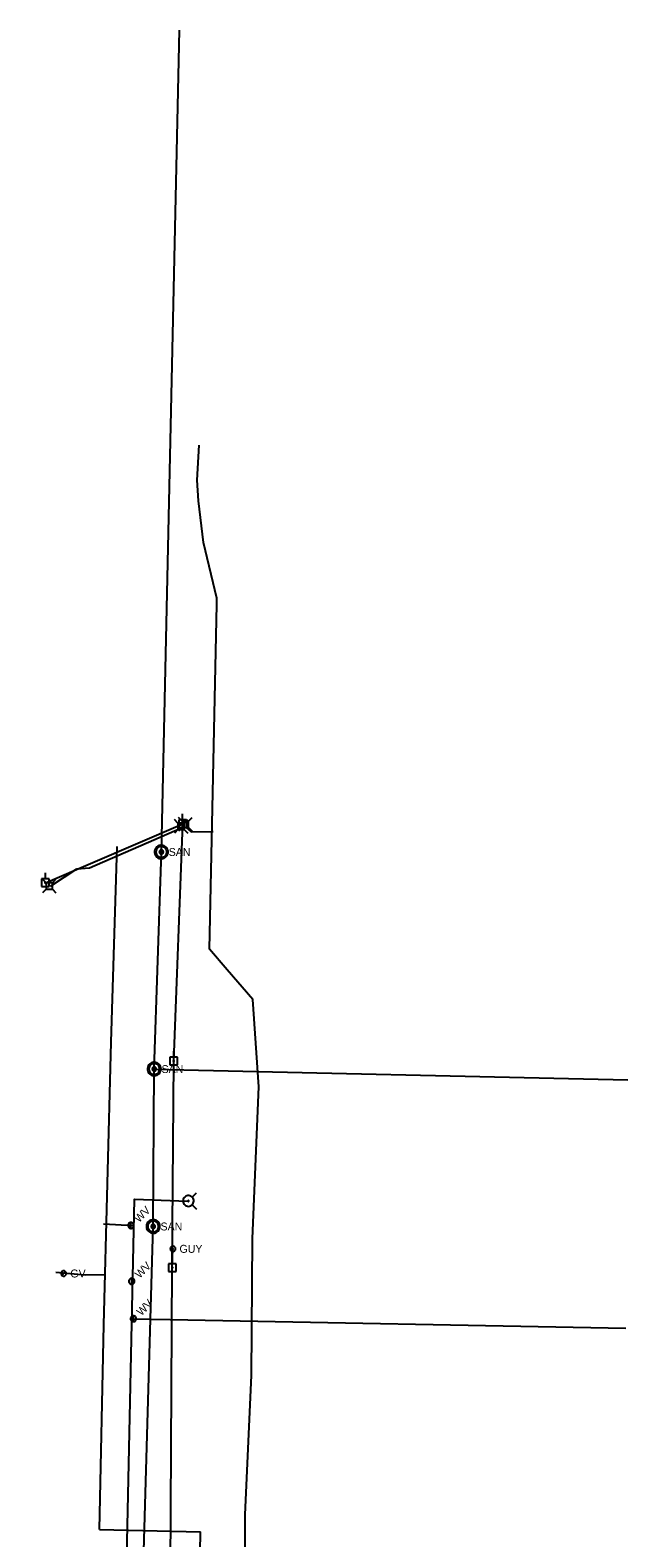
# Model space of a CAD drawing. Extents: x 596028 to 606371, y 330010 to 403088.
# Drawn here: x 596433 to 596723, y 343578 to 344310 of the extents above; entities that cross this region are included whole.
import ezdxf

# ---------------------------------------------------------------- set-up
doc = ezdxf.new("R2010")
doc.units = 0
for name, color, linetype in [('E_UTL_EGuyWire', 7, 'Continuous'), ('E_UTL_EPowerPole', 7, 'Continuous'), ('E_UTL_FO_UG', 7, 'Continuous'), ('E_UTL_G', 7, 'Continuous'), ('E_UTL_G_UG', 7, 'Continuous'), ('E_UTL_Overhead', 7, 'Continuous'), ('E_UTL_SAN_MH', 7, 'Continuous'), ('E_UTL_SAN_UG', 7, 'Continuous'), ('E_UTL_T', 7, 'Continuous'), ('E_UTL_T_UG', 7, 'Continuous'), ('E_UTL_W', 7, 'Continuous'), ('E_UTL_W_UG', 7, 'Continuous'), ('E_UTL_WHydrant', 7, 'Continuous')]:
    doc.layers.add(name, color=color, linetype=linetype)

msp = doc.modelspace()

# ---------------------------------------------------------------- linework, layer by layer
at = {"layer": 'E_UTL_EGuyWire'}
msp.add_line((596502.11, 343708.76), (596502.4, 343717.87), dxfattribs=at)
for points in [[(596503.68, 343717.87), (596503.66, 343718.12), (596503.59, 343718.35), (596503.48, 343718.57), (596503.32, 343718.76), (596503.14, 343718.92), (596502.93, 343719.04), (596502.7, 343719.12), (596502.46, 343719.15), (596502.21, 343719.14), (596501.98, 343719.09), (596501.75, 343718.98), (596501.56, 343718.84), (596501.39, 343718.67), (596501.26, 343718.46), (596501.16, 343718.23), (596501.12, 343717.99), (596501.12, 343717.75), (596501.16, 343717.51), (596501.26, 343717.28), (596501.39, 343717.08), (596501.56, 343716.9), (596501.75, 343716.76), (596501.98, 343716.66), (596502.21, 343716.6), (596502.46, 343716.59), (596502.7, 343716.63), (596502.93, 343716.71), (596503.14, 343716.83), (596503.32, 343716.99), (596503.48, 343717.18), (596503.59, 343717.4), (596503.66, 343717.63), (596503.68, 343717.87)], [(596502.56, 343717.87), (596502.55, 343717.9), (596502.54, 343717.93), (596502.53, 343717.96), (596502.51, 343717.98), (596502.49, 343718), (596502.46, 343718.02), (596502.43, 343718.03), (596502.4, 343718.03), (596502.37, 343718.03), (596502.34, 343718.02), (596502.32, 343718.01), (596502.29, 343717.99), (596502.27, 343717.97), (596502.25, 343717.95), (596502.24, 343717.92), (596502.24, 343717.89), (596502.24, 343717.86), (596502.24, 343717.83), (596502.25, 343717.8), (596502.27, 343717.77), (596502.29, 343717.75), (596502.32, 343717.73), (596502.34, 343717.72), (596502.37, 343717.71), (596502.4, 343717.71), (596502.43, 343717.72), (596502.46, 343717.73), (596502.49, 343717.74), (596502.51, 343717.76), (596502.53, 343717.79), (596502.54, 343717.81), (596502.55, 343717.84), (596502.56, 343717.87)]]:
    msp.add_lwpolyline(points, dxfattribs=at)
at = {"layer": 'E_UTL_EPowerPole'}
for points in [[(596507.14, 343926.17), (596507.14, 343929.08)], [(596508.99, 343926.17), (596505.3, 343926.17)], [(596505.3, 343926.17), (596505.3, 343922.48)], [(596505.3, 343922.48), (596508.99, 343922.48)], [(596507.41, 343924.33), (596507.41, 343924.38), (596507.4, 343924.42), (596507.38, 343924.46), (596507.35, 343924.5), (596507.31, 343924.53), (596507.27, 343924.55), (596507.23, 343924.56), (596507.19, 343924.57), (596507.14, 343924.57), (596507.1, 343924.56), (596507.06, 343924.54), (596507.02, 343924.51), (596506.99, 343924.48), (596506.96, 343924.44), (596506.95, 343924.4), (596506.94, 343924.35), (596506.94, 343924.31), (596506.95, 343924.26), (596506.96, 343924.22), (596506.99, 343924.18), (596507.02, 343924.15), (596507.06, 343924.13), (596507.1, 343924.11), (596507.14, 343924.1), (596507.19, 343924.09), (596507.23, 343924.1), (596507.27, 343924.12), (596507.31, 343924.14), (596507.35, 343924.17), (596507.38, 343924.2), (596507.4, 343924.24), (596507.41, 343924.29), (596507.41, 343924.33)], [(596508.99, 343922.48), (596508.99, 343926.17)], [(596440.48, 343897.51), (596440.48, 343900.42)], [(596442.32, 343897.51), (596438.64, 343897.51)], [(596438.64, 343897.51), (596438.64, 343893.82)], [(596438.64, 343893.82), (596442.32, 343893.82)], [(596440.75, 343895.67), (596440.75, 343895.72), (596440.73, 343895.76), (596440.71, 343895.8), (596440.69, 343895.84), (596440.65, 343895.87), (596440.61, 343895.89), (596440.57, 343895.9), (596440.52, 343895.91), (596440.48, 343895.91), (596440.44, 343895.9), (596440.39, 343895.88), (596440.36, 343895.85), (596440.33, 343895.82), (596440.3, 343895.78), (596440.28, 343895.74), (596440.28, 343895.69), (596440.28, 343895.65), (596440.28, 343895.6), (596440.3, 343895.56), (596440.33, 343895.52), (596440.36, 343895.49), (596440.39, 343895.47), (596440.44, 343895.45), (596440.48, 343895.44), (596440.52, 343895.43), (596440.57, 343895.44), (596440.61, 343895.46), (596440.65, 343895.48), (596440.69, 343895.51), (596440.71, 343895.54), (596440.73, 343895.58), (596440.75, 343895.63), (596440.75, 343895.67)], [(596442.32, 343893.82), (596442.32, 343897.51)], [(596502.8, 343810.92), (596502.8, 343813.83)], [(596504.64, 343810.92), (596500.96, 343810.92)], [(596500.96, 343810.92), (596500.96, 343807.23)], [(596500.96, 343807.23), (596504.64, 343807.23)], [(596503.07, 343809.08), (596503.07, 343809.13), (596503.05, 343809.17), (596503.03, 343809.21), (596503.01, 343809.24), (596502.97, 343809.27), (596502.93, 343809.3), (596502.89, 343809.31), (596502.84, 343809.32), (596502.8, 343809.32), (596502.76, 343809.31), (596502.71, 343809.29), (596502.68, 343809.26), (596502.65, 343809.23), (596502.62, 343809.19), (596502.6, 343809.15), (596502.6, 343809.1), (596502.6, 343809.06), (596502.6, 343809.01), (596502.62, 343808.97), (596502.65, 343808.93), (596502.68, 343808.9), (596502.71, 343808.87), (596502.76, 343808.85), (596502.8, 343808.84), (596502.84, 343808.84), (596502.89, 343808.85), (596502.93, 343808.86), (596502.97, 343808.89), (596503.01, 343808.92), (596503.03, 343808.95), (596503.05, 343808.99), (596503.07, 343809.03), (596503.07, 343809.08)], [(596504.64, 343807.23), (596504.64, 343810.92)], [(596503.93, 343710.61), (596500.24, 343710.61)], [(596500.24, 343710.61), (596500.24, 343706.92)], [(596502.08, 343710.61), (596502.08, 343713.52)], [(596503.93, 343706.92), (596503.93, 343710.61)], [(596500.24, 343706.92), (596503.93, 343706.92)], [(596502.35, 343708.76), (596502.35, 343708.81), (596502.34, 343708.85), (596502.31, 343708.89), (596502.29, 343708.93), (596502.25, 343708.96), (596502.21, 343708.98), (596502.17, 343709), (596502.13, 343709), (596502.08, 343709), (596502.04, 343708.99), (596501.99, 343708.97), (596501.96, 343708.94), (596501.93, 343708.91), (596501.9, 343708.87), (596501.89, 343708.83), (596501.88, 343708.79), (596501.88, 343708.74), (596501.89, 343708.7), (596501.9, 343708.65), (596501.93, 343708.62), (596501.96, 343708.58), (596501.99, 343708.56), (596502.04, 343708.54), (596502.08, 343708.53), (596502.13, 343708.53), (596502.17, 343708.53), (596502.21, 343708.55), (596502.25, 343708.57), (596502.29, 343708.6), (596502.31, 343708.64), (596502.34, 343708.68), (596502.35, 343708.72), (596502.35, 343708.76)]]:
    msp.add_lwpolyline(points, dxfattribs=at)
at = {"layer": 'E_UTL_FO_UG'}
for points in [[(596523.66, 344030.75), (596523.71, 344033.82), (596517.34, 344060.93), (596514.76, 344081.2), (596514.24, 344091.22), (596515.2, 344108.17)], [(596528.82, 343853.36), (596520.12, 343863.42), (596523.66, 344030.75)], [(596623.2, 343221.5), (596591.63, 343263.11), (596564.61, 343305.57), (596536.54, 343354.45), (596533.7, 343373.6), (596535.42, 343430.17), (596534.15, 343442.91), (596537.51, 343537.7), (596537.51, 343588.84), (596540.54, 343656.31), (596541, 343722.96), (596544.11, 343796.55), (596541.22, 343839.02), (596528.82, 343853.36)]]:
    msp.add_lwpolyline(points, dxfattribs=at)
at = {"layer": 'E_UTL_G'}
for points in [[(596450.68, 343705.9), (596450.66, 343706.15), (596450.59, 343706.38), (596450.48, 343706.6), (596450.33, 343706.79), (596450.14, 343706.95), (596449.93, 343707.07), (596449.7, 343707.15), (596449.46, 343707.18), (596449.22, 343707.17), (596448.98, 343707.12), (596448.76, 343707.01), (596448.56, 343706.87), (596448.39, 343706.7), (596448.26, 343706.49), (596448.17, 343706.26), (596448.12, 343706.02), (596448.12, 343705.78), (596448.17, 343705.54), (596448.26, 343705.31), (596448.39, 343705.11), (596448.56, 343704.93), (596448.76, 343704.79), (596448.98, 343704.69), (596449.22, 343704.63), (596449.46, 343704.62), (596449.7, 343704.66), (596449.93, 343704.74), (596450.14, 343704.86), (596450.33, 343705.02), (596450.48, 343705.21), (596450.59, 343705.43), (596450.66, 343705.66), (596450.68, 343705.9)], [(596448.49, 343705), (596450.31, 343706.81)]]:
    msp.add_lwpolyline(points, dxfattribs=at)
at = {"layer": 'E_UTL_G_UG'}
for p, q in [((596466.69, 343581.56), (596468.8, 343680.99)), ((596466.69, 343581.56), (596515.88, 343580.52)), ((596512.85, 343437.73), (596515.88, 343580.52))]:
    msp.add_line(p, q, dxfattribs=at)
for points in [[(596468.8, 343680.99), (596472.42, 343818.28), (596472.42, 343818.28), (596472.42, 343818.28), (596475.26, 343913.27)], [(596445.53, 343706.55), (596459.73, 343705.25), (596469.24, 343705.46)]]:
    msp.add_lwpolyline(points, dxfattribs=at)
at = {"layer": 'E_UTL_Overhead'}
msp.add_line((596440.51, 343895.67), (596507.18, 343924.33), dxfattribs=at)
msp.add_lwpolyline([(596433.09, 343338.93), (596500.33, 343406.37), (596501.29, 343562.28), (596502.11, 343708.76), (596502.83, 343809.08), (596507.18, 343924.33)], dxfattribs=at)
at = {"layer": 'E_UTL_SAN_MH'}
for points in [[(596500.1, 343910.62), (596500.04, 343911.25), (596499.86, 343911.85), (596499.57, 343912.41), (596499.19, 343912.9), (596498.71, 343913.31), (596498.17, 343913.62), (596497.58, 343913.83), (596496.95, 343913.92), (596496.33, 343913.89), (596495.72, 343913.74), (596495.15, 343913.48), (596494.64, 343913.12), (596494.2, 343912.66), (596493.86, 343912.14), (596493.63, 343911.55), (596493.51, 343910.94), (596493.51, 343910.31), (596493.63, 343909.69), (596493.86, 343909.11), (596494.2, 343908.58), (596494.64, 343908.13), (596495.15, 343907.77), (596495.72, 343907.5), (596496.33, 343907.36), (596496.95, 343907.33), (596497.58, 343907.42), (596498.17, 343907.62), (596498.71, 343907.93), (596499.19, 343908.35), (596499.57, 343908.84), (596499.86, 343909.4), (596500.04, 343910), (596500.1, 343910.62)], [(596499.44, 343910.62), (596499.39, 343911.12), (596499.25, 343911.6), (596499.02, 343912.05), (596498.71, 343912.44), (596498.33, 343912.77), (596497.89, 343913.02), (596497.42, 343913.19), (596496.92, 343913.26), (596496.42, 343913.24), (596495.93, 343913.12), (596495.48, 343912.91), (596495.07, 343912.62), (596494.72, 343912.25), (596494.45, 343911.83), (596494.26, 343911.37), (596494.17, 343910.87), (596494.17, 343910.37), (596494.26, 343909.88), (596494.45, 343909.41), (596494.72, 343908.99), (596495.07, 343908.63), (596495.48, 343908.34), (596495.93, 343908.13), (596496.42, 343908.01), (596496.92, 343907.99), (596497.42, 343908.06), (596497.89, 343908.22), (596498.33, 343908.47), (596498.71, 343908.8), (596499.02, 343909.2), (596499.25, 343909.64), (596499.39, 343910.12), (596499.44, 343910.62)], [(596497.79, 343910.62), (596497.77, 343910.81), (596497.72, 343910.99), (596497.63, 343911.16), (596497.51, 343911.31), (596497.37, 343911.43), (596497.21, 343911.52), (596497.03, 343911.59), (596496.84, 343911.61), (596496.66, 343911.6), (596496.47, 343911.56), (596496.3, 343911.48), (596496.15, 343911.37), (596496.02, 343911.23), (596495.92, 343911.08), (596495.85, 343910.9), (596495.81, 343910.72), (596495.81, 343910.53), (596495.85, 343910.34), (596495.92, 343910.17), (596496.02, 343910.01), (596496.15, 343909.87), (596496.3, 343909.77), (596496.47, 343909.69), (596496.66, 343909.64), (596496.84, 343909.63), (596497.03, 343909.66), (596497.21, 343909.72), (596497.37, 343909.82), (596497.51, 343909.94), (596497.63, 343910.09), (596497.72, 343910.25), (596497.77, 343910.44), (596497.79, 343910.62)], [(596496.63, 343805.21), (596496.57, 343805.83), (596496.4, 343806.43), (596496.11, 343806.99), (596495.72, 343807.48), (596495.25, 343807.89), (596494.7, 343808.21), (596494.11, 343808.41), (596493.49, 343808.5), (596492.86, 343808.47), (596492.25, 343808.32), (596491.68, 343808.06), (596491.17, 343807.7), (596490.74, 343807.25), (596490.4, 343806.72), (596490.17, 343806.14), (596490.05, 343805.52), (596490.05, 343804.89), (596490.17, 343804.28), (596490.4, 343803.69), (596490.74, 343803.17), (596491.17, 343802.71), (596491.68, 343802.35), (596492.25, 343802.09), (596492.86, 343801.94), (596493.49, 343801.91), (596494.11, 343802), (596494.7, 343802.2), (596495.25, 343802.52), (596495.72, 343802.93), (596496.11, 343803.42), (596496.4, 343803.98), (596496.57, 343804.58), (596496.63, 343805.21)], [(596495.97, 343805.21), (596495.93, 343805.71), (596495.78, 343806.19), (596495.55, 343806.63), (596495.24, 343807.03), (596494.86, 343807.36), (596494.43, 343807.61), (596493.96, 343807.77), (596493.46, 343807.84), (596492.96, 343807.82), (596492.47, 343807.7), (596492.01, 343807.49), (596491.6, 343807.2), (596491.26, 343806.84), (596490.99, 343806.42), (596490.8, 343805.95), (596490.7, 343805.46), (596490.7, 343804.95), (596490.8, 343804.46), (596490.99, 343804), (596491.26, 343803.57), (596491.6, 343803.21), (596492.01, 343802.92), (596492.47, 343802.71), (596492.96, 343802.59), (596493.46, 343802.57), (596493.96, 343802.64), (596494.43, 343802.8), (596494.86, 343803.06), (596495.24, 343803.38), (596495.55, 343803.78), (596495.78, 343804.22), (596495.93, 343804.71), (596495.97, 343805.21)], [(596494.32, 343805.21), (596494.31, 343805.39), (596494.25, 343805.57), (596494.17, 343805.74), (596494.05, 343805.89), (596493.91, 343806.01), (596493.74, 343806.11), (596493.57, 343806.17), (596493.38, 343806.19), (596493.19, 343806.19), (596493.01, 343806.14), (596492.84, 343806.06), (596492.68, 343805.95), (596492.55, 343805.82), (596492.45, 343805.66), (596492.38, 343805.48), (596492.35, 343805.3), (596492.35, 343805.11), (596492.38, 343804.93), (596492.45, 343804.75), (596492.55, 343804.59), (596492.68, 343804.46), (596492.84, 343804.35), (596493.01, 343804.27), (596493.19, 343804.23), (596493.38, 343804.22), (596493.57, 343804.24), (596493.74, 343804.31), (596493.91, 343804.4), (596494.05, 343804.52), (596494.17, 343804.67), (596494.25, 343804.84), (596494.31, 343805.02), (596494.32, 343805.21)], [(596496.13, 343728.76), (596496.07, 343729.38), (596495.89, 343729.99), (596495.61, 343730.54), (596495.22, 343731.04), (596494.74, 343731.45), (596494.2, 343731.76), (596493.61, 343731.97), (596492.99, 343732.06), (596492.36, 343732.03), (596491.75, 343731.88), (596491.18, 343731.62), (596490.67, 343731.25), (596490.24, 343730.8), (596489.9, 343730.27), (596489.66, 343729.69), (596489.54, 343729.07), (596489.54, 343728.45), (596489.66, 343727.83), (596489.9, 343727.25), (596490.24, 343726.72), (596490.67, 343726.26), (596491.18, 343725.9), (596491.75, 343725.64), (596492.36, 343725.49), (596492.99, 343725.46), (596493.61, 343725.55), (596494.2, 343725.76), (596494.74, 343726.07), (596495.22, 343726.48), (596495.61, 343726.97), (596495.89, 343727.53), (596496.07, 343728.13), (596496.13, 343728.76)], [(596495.47, 343728.76), (596495.42, 343729.26), (596495.28, 343729.74), (596495.05, 343730.19), (596494.74, 343730.58), (596494.36, 343730.91), (596493.93, 343731.16), (596493.45, 343731.32), (596492.95, 343731.4), (596492.45, 343731.37), (596491.97, 343731.25), (596491.51, 343731.05), (596491.1, 343730.75), (596490.75, 343730.39), (596490.48, 343729.97), (596490.3, 343729.5), (596490.2, 343729.01), (596490.2, 343728.51), (596490.3, 343728.02), (596490.48, 343727.55), (596490.75, 343727.13), (596491.1, 343726.76), (596491.51, 343726.47), (596491.97, 343726.26), (596492.45, 343726.15), (596492.95, 343726.12), (596493.45, 343726.19), (596493.93, 343726.36), (596494.36, 343726.61), (596494.74, 343726.94), (596495.05, 343727.33), (596495.28, 343727.78), (596495.42, 343728.26), (596495.47, 343728.76)], [(596493.82, 343728.76), (596493.8, 343728.95), (596493.75, 343729.13), (596493.66, 343729.29), (596493.55, 343729.44), (596493.4, 343729.57), (596493.24, 343729.66), (596493.06, 343729.72), (596492.88, 343729.75), (596492.69, 343729.74), (596492.51, 343729.69), (596492.33, 343729.62), (596492.18, 343729.51), (596492.05, 343729.37), (596491.95, 343729.21), (596491.88, 343729.04), (596491.84, 343728.85), (596491.84, 343728.66), (596491.88, 343728.48), (596491.95, 343728.31), (596492.05, 343728.15), (596492.18, 343728.01), (596492.33, 343727.9), (596492.51, 343727.82), (596492.69, 343727.78), (596492.88, 343727.77), (596493.06, 343727.8), (596493.24, 343727.86), (596493.4, 343727.95), (596493.55, 343728.08), (596493.66, 343728.22), (596493.75, 343728.39), (596493.8, 343728.57), (596493.82, 343728.76)]]:
    msp.add_lwpolyline(points, dxfattribs=at)
at = {"layer": 'E_UTL_SAN_UG'}
msp.add_line((596493.38, 343805.11), (596723.32, 343799.88), dxfattribs=at)
msp.add_lwpolyline([(596474.29, 343299.7), (596483.68, 343369.67), (596488.27, 343570.99), (596492.83, 343728.76), (596493.38, 343805.11), (596496.8, 343910.62), (596505.55, 344309.74)], dxfattribs=at)
at = {"layer": 'E_UTL_T'}
for points in [[(596504.85, 343924.67), (596503.1, 343926.43)], [(596504.85, 343921.58), (596503.1, 343919.83)], [(596507.95, 343924.67), (596504.85, 343924.67)], [(596504.85, 343924.67), (596504.85, 343921.58)], [(596504.85, 343921.58), (596507.95, 343921.58)], [(596506.85, 343925.54), (596505.1, 343927.3)], [(596506.85, 343922.45), (596505.1, 343920.7)], [(596509.95, 343925.54), (596506.85, 343925.54)], [(596506.85, 343925.54), (596506.85, 343922.45)], [(596506.85, 343922.45), (596509.95, 343922.45)], [(596507.95, 343924.67), (596509.7, 343926.43)], [(596507.95, 343921.58), (596507.95, 343924.67)], [(596507.95, 343921.58), (596509.7, 343919.83)], [(596509.95, 343925.54), (596511.7, 343927.3)], [(596509.95, 343922.45), (596509.95, 343925.54)], [(596509.95, 343922.45), (596511.7, 343920.7)], [(596440.79, 343895.58), (596439.03, 343897.34)], [(596440.79, 343892.49), (596439.03, 343890.74)], [(596443.88, 343895.58), (596440.79, 343895.58)], [(596440.79, 343895.58), (596440.79, 343892.49)], [(596440.79, 343892.49), (596443.88, 343892.49)], [(596443.88, 343895.58), (596445.63, 343897.34)], [(596443.88, 343892.49), (596443.88, 343895.58)], [(596443.88, 343892.49), (596445.63, 343890.74)]]:
    msp.add_lwpolyline(points, dxfattribs=at)
at = {"layer": 'E_UTL_T_UG'}
msp.add_line((596461.96, 343902.9), (596506.85, 343922.45), dxfattribs=at)
for points in [[(596508.87, 343922.54), (596511.3, 343920.33)], [(596511.3, 343920.33), (596521.91, 343920.5)], [(596442.96, 343894), (596455.75, 343902.44)], [(596455.75, 343902.44), (596461.96, 343902.9)]]:
    msp.add_lwpolyline(points, dxfattribs=at)
at = {"layer": 'E_UTL_W'}
for points in [[(596483.04, 343730.24), (596482.83, 343730.41), (596482.6, 343730.54), (596482.34, 343730.62), (596482.07, 343730.66), (596481.8, 343730.64), (596481.54, 343730.57), (596481.29, 343730.45), (596481.08, 343730.29), (596480.89, 343730.09), (596480.75, 343729.85), (596480.66, 343729.6), (596480.61, 343729.33), (596480.62, 343729.06), (596480.68, 343728.8), (596480.78, 343728.55), (596480.94, 343728.32), (596481.13, 343728.13), (596481.35, 343727.98), (596481.6, 343727.87), (596481.87, 343727.82), (596482.14, 343727.81), (596482.4, 343727.85), (596482.66, 343727.95), (596482.89, 343728.09), (596483.09, 343728.27), (596483.25, 343728.49), (596483.37, 343728.73), (596483.44, 343728.99), (596483.46, 343729.27), (596483.43, 343729.53), (596483.35, 343729.79), (596483.22, 343730.03), (596483.04, 343730.24)], [(596482.04, 343727.81), (596482.04, 343730.66)], [(596483.4, 343703.15), (596483.19, 343703.32), (596482.95, 343703.45), (596482.7, 343703.53), (596482.43, 343703.56), (596482.16, 343703.54), (596481.89, 343703.47), (596481.65, 343703.36), (596481.43, 343703.19), (596481.25, 343702.99), (596481.11, 343702.76), (596481.01, 343702.51), (596480.97, 343702.24), (596480.98, 343701.97), (596481.03, 343701.7), (596481.14, 343701.45), (596481.29, 343701.23), (596481.48, 343701.04), (596481.71, 343700.89), (596481.96, 343700.78), (596482.22, 343700.72), (596482.49, 343700.72), (596482.76, 343700.76), (596483.02, 343700.86), (596483.25, 343701), (596483.45, 343701.18), (596483.61, 343701.4), (596483.73, 343701.64), (596483.8, 343701.9), (596483.82, 343702.17), (596483.79, 343702.44), (596483.7, 343702.7), (596483.57, 343702.94), (596483.4, 343703.15)], [(596482.39, 343700.71), (596482.39, 343703.56)], [(596484.21, 343684.95), (596484, 343685.12), (596483.76, 343685.25), (596483.5, 343685.33), (596483.23, 343685.37), (596482.96, 343685.35), (596482.7, 343685.28), (596482.45, 343685.16), (596482.24, 343685), (596482.06, 343684.79), (596481.91, 343684.56), (596481.82, 343684.31), (596481.77, 343684.04), (596481.78, 343683.77), (596481.84, 343683.51), (596481.95, 343683.26), (596482.1, 343683.03), (596482.29, 343682.84), (596482.51, 343682.69), (596482.76, 343682.58), (596483.03, 343682.52), (596483.3, 343682.52), (596483.57, 343682.56), (596483.82, 343682.66), (596484.05, 343682.8), (596484.25, 343682.98), (596484.41, 343683.2), (596484.53, 343683.44), (596484.6, 343683.7), (596484.62, 343683.97), (596484.59, 343684.24), (596484.51, 343684.5), (596484.38, 343684.74), (596484.21, 343684.95)], [(596483.2, 343682.51), (596483.2, 343685.37)]]:
    msp.add_lwpolyline(points, dxfattribs=at)
at = {"layer": 'E_UTL_W_UG'}
for p, q in [((596468.67, 343730), (596483.07, 343729.2)), ((596482.47, 343683.84), (596501, 343683.49)), ((596501, 343683.49), (596722.27, 343679.3))]:
    msp.add_line(p, q, dxfattribs=at)
msp.add_lwpolyline([(596502.84, 343266.57), (596534.18, 343288.36), (596475.61, 343364.22), (596483.72, 343742), (596509.64, 343741.09)], dxfattribs=at)
at = {"layer": 'E_UTL_WHydrant'}
for points in [[(596509.93, 343738.5), (596510.43, 343738.55), (596510.9, 343738.69), (596511.35, 343738.92), (596511.74, 343739.22), (596512.07, 343739.6), (596512.31, 343740.03), (596512.48, 343740.5), (596512.55, 343741), (596512.53, 343741.5), (596512.41, 343741.98), (596512.2, 343742.43), (596511.91, 343742.84), (596511.55, 343743.18), (596511.13, 343743.45), (596510.67, 343743.64), (596510.18, 343743.73), (596509.68, 343743.73), (596509.19, 343743.64), (596508.73, 343743.45), (596508.31, 343743.18), (596507.95, 343742.84), (596507.66, 343742.43), (596507.45, 343741.98), (596507.33, 343741.5), (596507.31, 343741), (596507.38, 343740.5), (596507.54, 343740.03), (596507.79, 343739.6), (596508.12, 343739.22), (596508.51, 343738.92), (596508.95, 343738.69), (596509.43, 343738.55), (596509.93, 343738.5)], [(596509.93, 343740.92), (596509.97, 343740.93), (596510, 343740.94), (596510.04, 343740.95), (596510.07, 343740.98), (596510.09, 343741.01), (596510.11, 343741.04), (596510.12, 343741.07), (596510.13, 343741.11), (596510.13, 343741.15), (596510.12, 343741.19), (596510.1, 343741.22), (596510.08, 343741.25), (596510.05, 343741.28), (596510.02, 343741.3), (596509.99, 343741.31), (596509.95, 343741.32), (596509.91, 343741.32), (596509.87, 343741.31), (596509.84, 343741.3), (596509.8, 343741.28), (596509.78, 343741.25), (596509.76, 343741.22), (596509.74, 343741.19), (596509.73, 343741.15), (596509.73, 343741.11), (596509.73, 343741.07), (596509.75, 343741.04), (596509.77, 343741.01), (596509.79, 343740.98), (596509.82, 343740.95), (596509.85, 343740.94), (596509.89, 343740.93), (596509.93, 343740.92)], [(596511.76, 343742.96), (596513.91, 343745.1)], [(596511.76, 343739.29), (596513.91, 343737.14)]]:
    msp.add_lwpolyline(points, dxfattribs=at)

# ---------------------------------------------------------------- texts
at = {"layer": 'E_UTL_EGuyWire'}
msp.add_text('GUY', height=3.85, rotation=360, dxfattribs=at).set_placement((596505.6, 343715.95))
at = {"layer": 'E_UTL_G'}
msp.add_text('GV', height=3.85, dxfattribs=at).set_placement((596452.61, 343703.98))
at = {"layer": 'E_UTL_SAN_MH'}
for p in [(596500.36, 343908.68), (596496.9, 343803.26), (596496.39, 343726.81)]:
    msp.add_text('SAN', height=3.849, dxfattribs=at).set_placement(p)
at = {"layer": 'E_UTL_W'}
for p in [(596485.92, 343730.39), (596486.27, 343703.3), (596487.08, 343685.1)]:
    msp.add_text('WV', height=3.85, rotation=45, dxfattribs=at).set_placement(p)

doc.saveas('drawing.dxf')
